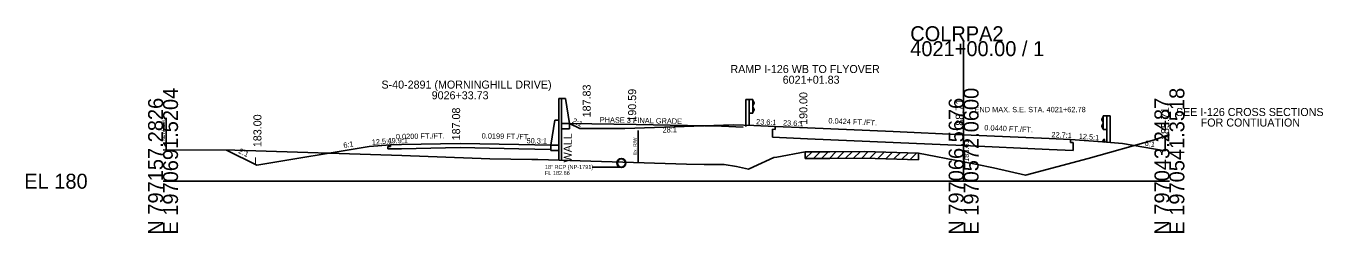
# Model space of a CAD drawing. Extents: x -26 to 1971083, y -10 to 798159.
# Drawn here: x -25.7 to 217.3, y 4490.3 to 4529 of the extents above; entities that cross this region are included whole.
import ezdxf

# ---------------------------------------------------------------- set-up
doc = ezdxf.new("R2010")
doc.units = 0
for name, color, linetype in [('RD_GPK_XS_Cell', 7, 'Continuous'), ('RD_XS_Base', 7, 'Continuous'), ('RD_XS_Box', 7, 'Continuous'), ('RD_XS_CurbTop', 7, 'Continuous'), ('RD_XS_EarthShd', 7, 'Continuous'), ('RD_XS_ExGround', 7, 'Continuous'), ('RD_XS_ExPaveRet', 7, 'Continuous'), ('RD_XS_ExRW', 7, 'Continuous'), ('RD_XS_GR', 7, 'Continuous'), ('RD_XS_MedBWall', 7, 'Continuous'), ('RD_XS_Misc_Line', 7, 'Continuous'), ('RD_XS_NewRW', 7, 'Continuous'), ('RD_XS_Pave', 7, 'Continuous'), ('RD_XS_PaveShd', 7, 'Continuous'), ('RD_XS_Pipe', 7, 'Continuous'), ('RD_XS_TieSlope', 7, 'Continuous'), ('RD_XS_TX_Elev_EX', 7, 'Continuous'), ('RD_XS_TX_Elev_PR', 7, 'Continuous'), ('RD_XS_TX_Misc', 7, 'Continuous'), ('RD_XS_TX_MkPT', 7, 'Continuous'), ('RD_XS_TX_Notes', 7, 'Continuous'), ('RD_XS_TX_Profile', 7, 'Continuous'), ('RD_XS_TX_ShdSlope', 7, 'Continuous'), ('RD_XS_TX_Slope', 7, 'Continuous'), ('RD_XS_TX_Station', 7, 'Continuous')]:
    doc.layers.add(name, color=color, linetype=linetype)

msp = doc.modelspace()

# ---------------------------------------------------------------- linework, layer by layer
at = {"layer": 'RD_GPK_XS_Cell'}
for p, q in [((150, 4500), (150, 4526.2)), ((0, 4500), (150, 4500)), ((150, 4500), (188.56, 4500))]:
    msp.add_line(p, q, dxfattribs=at)
at = {"layer": 'RD_XS_Base'}
for p, q in [((76.17, 4510.53), (76.17, 4510.83)), ((114.18, 4509.71), (114.68, 4509.69)), ((114.18, 4508.23), (114.18, 4509.71)), ((114.68, 4509.69), (114.68, 4510.25)), ((42.14, 4506.51), (42.64, 4506.52)), ((42.14, 4506.03), (42.14, 4506.51)), ((44.65, 4506.08), (42.14, 4506.03)), ((42.64, 4506.52), (42.64, 4506.82)), ((44.65, 4506.08), (55.66, 4506.3)), ((55.66, 4506.3), (66.67, 4506.08)), ((66.67, 4506.08), (72.67, 4505.96)), ((72.67, 4506.44), (72.67, 4506.74)), ((120.72, 4507.96), (114.18, 4508.23)), ((120.72, 4507.96), (136.82, 4507.27)), ((136.82, 4507.27), (150, 4506.67)), ((150, 4506.67), (166, 4505.96)), ((166, 4505.96), (170.5, 4505.77)), ((170, 4507.27), (170, 4507.83)), ((170.5, 4507.25), (170, 4507.27)), ((170.5, 4505.77), (170.5, 4507.25))]:
    msp.add_line(p, q, dxfattribs=at)
at = {"layer": 'RD_XS_Box'}
msp.add_line((74.67, 4515.5), (74.17, 4515.5), dxfattribs=at)
at = {"layer": 'RD_XS_CurbTop'}
for p, q in [((176, 4507.35), (176.25, 4507.8)), ((176, 4507.35), (176.47, 4507.31)), ((176.47, 4507.31), (176.41, 4507.75))]:
    msp.add_line(p, q, dxfattribs=at)
msp.add_ellipse((176.32, 4507.72), major_axis=(0, -0.131), ratio=0.686, start_param=1.762783, end_param=4.036677, dxfattribs=at)
at = {"layer": 'RD_XS_EarthShd'}
for p, q in [((114.68, 4510.25), (110.66, 4510.42)), ((42.64, 4506.82), (38.64, 4506.5)), ((170, 4507.83), (176, 4507.35))]:
    msp.add_line(p, q, dxfattribs=at)
at = {"layer": 'RD_XS_ExGround'}
msp.add_lwpolyline([(0, 4505.9), (13.42, 4505.79), (44.76, 4504.84), (61.25, 4504.18), (69.07, 4504.05), (70.25, 4504.04), (98.05, 4503.21), (101.36, 4503.1), (102.5, 4503.14), (105.14, 4503.14), (107.44, 4502.76), (109.71, 4502.28), (110.63, 4502.7), (114.41, 4504.42), (114.97, 4504.52), (120.33, 4505.48), (124.92, 4505.52), (131.39, 4505.59), (141.52, 4505.25), (150, 4503.61), (152.55, 4503.1), (155.57, 4502.48), (161.62, 4501.14), (173.32, 4504.26), (185.75, 4507.73), (188.56, 4508.73)], dxfattribs=at)
at = {"layer": 'RD_XS_ExPaveRet'}
for p, q in [((120.33, 4504.23), (120.33, 4505.48)), ((120.33, 4504.23), (124.92, 4504.27)), ((124.92, 4504.27), (131.39, 4504.34)), ((131.39, 4504.34), (141.52, 4504)), ((141.52, 4505.25), (141.52, 4504))]:
    msp.add_line(p, q, dxfattribs=at)
at = {"layer": 'RD_XS_ExRW'}
msp.add_line((89.01, 4509.51), (89.01, 4503.51), dxfattribs=at)
at = {"layer": 'RD_XS_GR'}
for p, q in [((109.84, 4515.3), (109.18, 4515.3)), ((109.18, 4515.3), (109.18, 4510.24)), ((110.51, 4515.3), (109.84, 4515.3)), ((109.84, 4515.3), (109.84, 4510.35)), ((110.51, 4512.73), (110.51, 4515.3)), ((110.51, 4515.13), (110.78, 4514.69)), ((110.78, 4514.58), (110.51, 4514.14)), ((110.78, 4513.44), (110.51, 4513.88)), ((110.51, 4512.89), (110.78, 4513.33)), ((110.78, 4514.69), (110.78, 4514.58)), ((110.78, 4513.33), (110.78, 4513.44)), ((110.51, 4512.73), (109.84, 4512.73)), ((176.15, 4512.06), (175.88, 4511.62)), ((175.88, 4511.62), (175.88, 4511.51)), ((175.88, 4511.51), (176.15, 4511.07)), ((175.88, 4510.36), (176.15, 4510.8)), ((176.15, 4512.22), (176.81, 4512.22)), ((176.15, 4509.65), (176.15, 4512.22)), ((176.81, 4512.22), (177.48, 4512.22)), ((176.81, 4512.22), (176.81, 4507.28)), ((177.48, 4512.22), (177.48, 4507.17)), ((175.88, 4510.25), (175.88, 4510.36)), ((176.15, 4509.81), (175.88, 4510.25)), ((176.15, 4509.65), (176.81, 4509.65))]:
    msp.add_line(p, q, dxfattribs=at)
at = {"layer": 'RD_XS_MedBWall'}
for p, q in [((74.17, 4515.5), (74.17, 4511.41)), ((74.67, 4515.5), (74.67, 4503.92)), ((74.67, 4509.85), (74.67, 4515.5)), ((75.42, 4515.5), (74.67, 4515.5)), ((76.17, 4510.83), (75.42, 4515.5)), ((72.67, 4506.74), (73.42, 4511.41)), ((73.42, 4511.41), (74.17, 4511.41)), ((74.17, 4505.76), (74.17, 4511.41)), ((74.67, 4510.83), (76.17, 4510.83)), ((76.17, 4509.83), (76.17, 4510.83)), ((76.17, 4509.83), (74.67, 4509.83)), ((74.17, 4506.74), (72.67, 4506.74)), ((72.67, 4505.74), (72.67, 4506.74)), ((72.67, 4505.74), (74.17, 4505.74)), ((74.17, 4503.93), (74.17, 4505.74))]:
    msp.add_line(p, q, dxfattribs=at)
at = {"layer": 'RD_XS_Misc_Line'}
for p, q in [((120.33, 4504.23), (121.6, 4505.49)), ((121.84, 4504.24), (123.11, 4505.5)), ((123.35, 4504.26), (124.62, 4505.52)), ((124.86, 4504.27), (126.13, 4505.53)), ((126.37, 4504.29), (127.64, 4505.55)), ((127.88, 4504.3), (129.15, 4505.57)), ((129.39, 4504.32), (130.66, 4505.58)), ((130.9, 4504.33), (132.14, 4505.56)), ((132.41, 4504.3), (133.63, 4505.51)), ((133.92, 4504.26), (135.14, 4505.46)), ((135.43, 4504.21), (136.65, 4505.42)), ((136.94, 4504.16), (138.16, 4505.37)), ((138.45, 4504.11), (139.67, 4505.32)), ((139.96, 4504.06), (141.18, 4505.27))]:
    msp.add_line(p, q, dxfattribs=at)
at = {"layer": 'RD_XS_NewRW'}
msp.add_line((0.61, 4511.89), (0.61, 4505.89), dxfattribs=at)
at = {"layer": 'RD_XS_Pave'}
for p, q in [((88.64, 4510.59), (104.66, 4510.29)), ((120.72, 4509.99), (136.82, 4509.31)), ((150, 4508.71), (166, 4508)), ((44.65, 4506.86), (55.66, 4507.08)), ((55.66, 4507.08), (66.67, 4506.86))]:
    msp.add_line(p, q, dxfattribs=at)
at = {"layer": 'RD_XS_PaveShd'}
for p, q in [((88.64, 4510.59), (76.17, 4510.83)), ((104.66, 4510.29), (108.67, 4510.13)), ((120.72, 4509.99), (114.68, 4510.25)), ((150, 4508.71), (136.82, 4509.31)), ((44.65, 4506.86), (42.64, 4506.82)), ((66.67, 4506.86), (72.67, 4506.74)), ((166, 4508), (170, 4507.83))]:
    msp.add_line(p, q, dxfattribs=at)
at = {"layer": 'RD_XS_Pipe'}
msp.add_line((85.38, 4502.66), (80.38, 4502.66), dxfattribs=at)
for radius in [0.85, 0.75]:
    msp.add_circle((85.88, 4503.41), radius, dxfattribs=at)
at = {"layer": 'RD_XS_TieSlope'}
for p, q in [((76.17, 4510.83), (78.11, 4509.87)), ((78.11, 4509.87), (86.49, 4509.87)), ((106.89, 4510.58), (86.49, 4509.87)), ((110.66, 4510.42), (106.89, 4510.58)), ((187.75, 4505.71), (187.75, 4508.45)), ((38.64, 4506.5), (17.59, 4503)), ((66.67, 4506.86), (66.67, 4506.86)), ((176, 4507.35), (179.75, 4507.05)), ((179.75, 4507.05), (187.75, 4505.71)), ((17.59, 4503), (11.91, 4505.83))]:
    msp.add_line(p, q, dxfattribs=at)

# ---------------------------------------------------------------- texts
at = {"layer": 'RD_GPK_XS_Cell'}
for s, p in [('COLRPA2', (140, 4526.2)), ('4021+00.00 / 1', (140, 4523.4)), ('EL 180', (-26, 4498.6))]:
    msp.add_text(s, height=2.8, dxfattribs=at).set_placement(p)
for s, p in [('E 1970691.5204', (2.8, 4490)), ('E 1970572.0600', (152.8, 4490)), ('E 1970541.3518', (191.36, 4490)), ('N 797157.2826', (0, 4490)), ('N 797066.5676', (150, 4490)), ('N 797043.2487', (188.56, 4490))]:
    msp.add_text(s, height=2.8, rotation=90, dxfattribs=at).set_placement(p)
at = {"layer": 'RD_XS_ExRW'}
msp.add_text('Ex. R/W ', height=0.65, rotation=90, dxfattribs=at).set_placement((88.76, 4504.89))
at = {"layer": 'RD_XS_MedBWall'}
msp.add_text(' WALL', height=1.5, rotation=90, dxfattribs=at).set_placement((76.58, 4502.96))
at = {"layer": 'RD_XS_NewRW'}
msp.add_text('NEW R/W ', height=0.65, rotation=90, dxfattribs=at).set_placement((0.34, 4507.45))
at = {"layer": 'RD_XS_Pipe'}
for s, p in [('18" RCP (NP-1791)', (71.54, 4502.29)), ('FL 182.66', (71.54, 4501.16))]:
    msp.add_text(s, height=0.75, dxfattribs=at).set_placement(p)
at = {"layer": 'RD_XS_TX_Elev_EX'}
msp.add_text('183.61', height=1, rotation=90, dxfattribs=at).set_placement((151, 4503.61))
at = {"layer": 'RD_XS_TX_Elev_PR'}
for s, p in [(' 190.59', (88.64, 4510.59)), (' 190.00', (120.72, 4509.99)), (' 187.08', (55.66, 4507.08)), (' 188.71', (150, 4508.71))]:
    msp.add_text(s, height=1.5, rotation=90, dxfattribs=at).set_placement(p)
at = {"layer": 'RD_XS_TX_Misc'}
for s, p in [('187.83', (80.12, 4511.95)), ('185.71', (188.5, 4507.71)), ('183.00', (18.43, 4506.37))]:
    msp.add_text(s, height=1.5, rotation=90, dxfattribs=at).set_placement(p)
at = {"layer": 'RD_XS_TX_MkPT'}
msp.add_text('L', height=1.5, dxfattribs=at).set_placement((17.08, 4503))
at = {"layer": 'RD_XS_TX_Notes'}
for s, height, p in [('END MAX. S.E. STA. 4021+62.78', 1, (152.04, 4512.91)), ('SEE I-126 CROSS SECTIONS', 1.5, (189.79, 4512.2)), ('FOR CONTIUATION', 1.5, (194.42, 4510.23))]:
    msp.add_text(s, height=height, dxfattribs=at).set_placement(p)
at = {"layer": 'RD_XS_TX_Profile'}
for s, rotation, p in [('49.9:1', 1.1477, (42.06, 4507.06)), ('50.3:1', 358.8604, (68.1, 4507.09))]:
    msp.add_text(s, height=1, rotation=rotation, dxfattribs=at).set_placement(p)
at = {"layer": 'RD_XS_TX_ShdSlope'}
for s, rotation, p in [('PHASE 3 FINAL GRADE', 358.9078, (81.81, 4511.01)), ('23.6:1', 357.5718, (111.1, 4510.65)), ('12.5:1', 355.4261, (171.54, 4507.95)), ('12.5:1', 4.5697, (39.15, 4506.79))]:
    msp.add_text(s, height=1, rotation=rotation, dxfattribs=at).set_placement(p)
at = {"layer": 'RD_XS_TX_Slope'}
for s, rotation, p in [('2:1', 333.5723, (76.57, 4510.98)), ('23.6:1', 357.5718, (116.13, 4510.44)), ('0.0424 FT./FT.', 357.5718, (124.64, 4510.83)), ('0.0200 FT./FT.', 1.1477, (43.63, 4507.84)), ('0.0199 FT./FT.', 358.8604, (59.69, 4508)), ('28:1', 1.529, (93.6, 4509.09)), ('0.0440 FT./FT.', 357.4806, (153.86, 4509.54)), ('22.7:1', 357.4806, (166.43, 4508.23)), ('2:1', 333.4561, (14.03, 4505.33)), ('6:1', 9.4537, (33.86, 4506.21)), ('6:1', 350.5377, (183.88, 4506.68))]:
    msp.add_text(s, height=1, rotation=rotation, dxfattribs=at).set_placement(p)
at = {"layer": 'RD_XS_TX_Station'}
for s, p in [('RAMP I-126 WB TO FLYOVER', (106.31, 4520.24)), ('S-40-2891 (MORNINGHILL DRIVE)', (40.92, 4517.33)), ('6021+01.83', (116.1, 4518.24)), ('9026+33.73', (50.33, 4515.33))]:
    msp.add_text(s, height=1.5, dxfattribs=at).set_placement(p)

doc.saveas('drawing.dxf')
